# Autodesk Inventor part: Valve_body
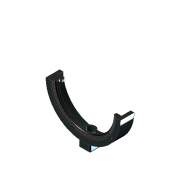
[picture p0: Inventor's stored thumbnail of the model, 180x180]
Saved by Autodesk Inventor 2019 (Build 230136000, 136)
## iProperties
Created: 2019-09
Part Number: Valve_body
Material: Steel, Cast
Document SubType Name: Modeling
Designer: Admin
Density: 7.85 g/cm^3
Appearance: Semi-Polished
Author: Admin
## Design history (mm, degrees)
sketch "Sketch1"
  geometry: L1 (0, 262.245)-(0, -275.534) reference; L2 (-162, 191.562)-(-162, -230.179); L3 (-147, -40.2)-(-162, -40.2); L4 (-162, -40.2)-(-162, 19.8); L5 (0, 0)-(-245.019, 0); L6 (-147, 0)-(-147, -40.2); L7 (-144, 19.8)-(-144, 14.657); L8 (-75.034, 9.8)-(-236.302, 9.8); L9 (-75.034, 14.657)-(-236.302, 14.657); L10 (-162, 19.8)-(-144, 19.8); L11 (-125, 9.8)-(-125, 0); L12 (-125, 0)-(-147, 0); L13 (-129.888, 17.396)-(-131.341, 17.768); L14 (-129.888, 17.396)-(-131.341, 17.768); L15 (-129.888, 17.396)-(-130.074, 16.67); L16 (-128.621, 16.298)-(-130.074, 16.67); L17 (-128.435, 17.025)-(-128.621, 16.298); L18 (-127.486, 16.782)-(-128.435, 17.025); L19 (-122.538, 20.488)-(-121.21, 24.915); L20 (-123.181, 9.313)-(-121.034, 17.713) reference; L21 (-123.286, 8.904)-(-119.75, 22.735); L22 (-146.331, 20.488)-(-146.331, 14.796); L23 (-125.304, -1.425)-(-149.651, -1.425); L24 (-146.331, 14.796)-(-125.304, 9.421); L25 (-121.21, 24.915)-(-124.087, 37.088); L26 (-125.304, 9.421)-(-125.304, -1.425); L27 (-123.644, 9.974)-(-123.644, 2.781); L28 (-123.644, 9.974)-(-118.392, 30.522) reference; L29 (-137.154, 19.254)-(-137.34, 18.527); L30 (-137.34, 18.527)-(-138.793, 18.899); L31 (-138.608, 19.625)-(-138.793, 18.899); L32 (-138.608, 19.625)-(-139.9, 19.956); L33 (-140.886, 16.097)-(-139.9, 19.956); L34 (-131.341, 17.768)-(-131.527, 17.041); L35 (-132.795, 18.139)-(-132.98, 17.413); L36 (-132.795, 18.139)-(-134.248, 18.511); L37 (-132.795, 18.139)-(-134.248, 18.511); L38 (-131.527, 17.041)-(-132.98, 17.413); L39 (-135.701, 18.882)-(-137.154, 19.254); L40 (-135.701, 18.882)-(-137.154, 19.254); L41 (-135.701, 18.882)-(-135.887, 18.156); L42 (-134.434, 17.784)-(-135.887, 18.156); L43 (-134.248, 18.511)-(-134.434, 17.784); L44 (-118.178, 12.338)-(-151.094, 20.753) reference; L45 (-141.514, 18.304)-(-141.131, 19.8); L46 (-144, 19.8)-(-141.131, 19.8); L47 (-144, 14.657)-(-138.677, 13.296); L48 (-128.477, 12.907)-(-129.425, 13.149); L49 (-129.425, 13.149)-(-129.24, 13.876); L50 (-129.24, 13.876)-(-130.693, 14.247); L51 (-130.879, 13.521)-(-130.693, 14.247); L52 (-130.879, 13.521)-(-132.332, 13.892); L53 (-132.332, 13.892)-(-132.146, 14.619); L54 (-132.146, 14.619)-(-133.6, 14.99); L55 (-133.785, 14.264)-(-133.6, 14.99); L56 (-133.785, 14.264)-(-135.239, 14.635); L57 (-135.239, 14.635)-(-135.053, 15.362); L58 (-135.053, 15.362)-(-136.506, 15.733); L59 (-136.692, 15.007)-(-136.506, 15.733); L60 (-136.692, 15.007)-(-138.145, 15.378); L61 (-138.145, 15.378)-(-137.959, 16.105); L62 (-137.959, 16.105)-(-139.413, 16.477); L63 (-139.598, 15.75)-(-139.413, 16.477); L64 (-139.598, 15.75)-(-140.89, 16.08)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; A1 r 4 centre (-126.495, 20.658) between (-127.486, 16.782) and (-124.45, 17.22); A2 r 4.5 centre (-122.148, 13.353) between (-121.034, 17.713) and (-124.45, 17.22); A3 r 4.17 centre (-122.148, 13.353) between (-125.656, 11.098) and (-123.181, 9.313); A4 r 4 centre (-129.02, 8.935) between (-125.656, 11.098) and (-128.03, 12.81); A5 r 7.167 centre (-123.225, 16.744) between (-129.425, 13.149) and (-125, 9.8); 3 further points
  constraints: 166 end point, 21 perpendicular, 18 symmetric about line, 11 point on circle, 10 point on line, 8 tangent, 6 collinear, 5 centre point, 5 horizontal, 5 vertical, 3 parallel, 1 midpoint, 5 other
  dimensions: "d0" = 162 distance between parallel lines of L2 L1; "d3" = 15 distance between parallel lines of L2 L6; "d4" = 18 distance between parallel lines of L2 L7; "d6" = 9.8 distance between parallel lines of L8 L5; "d8" = 5.143 distance between parallel lines of L9 L10; "d9" = 22 distance between parallel lines of L6 L11; "d10" = 60 distance of L3.end L4.end; "d157" = 2 distance between parallel lines of L32 L44; "d174" = 90 deg angle of L49 L48; "d175" = 19.8 distance between parallel lines of L5 L10; "d176" = 14.657 distance from line of L12 L7.end (derived); "d177" = 9.8 distance of L11.end L11.start (derived); "d178" = 7.16694 radius of A5 (derived); "d179" = 1.5 distance between parallel lines of L51 L49; "d180" = 1.45327 horizontal distance of L51.start L52.end; "d181" = 1.5 distance between parallel lines of L55 L53; "d182" = 1.45327 horizontal distance of L55.start L56.end; "d183" = 1.5 distance between parallel lines of L59 L57; "d184" = 1.45327 horizontal distance of L59.start L60.end; "d185" = 1.5 distance between parallel lines of L63 L61; "d186" = 1.29211 horizontal distance of L63.start L64.end; "d187" = 0.75 distance between parallel lines of L72 L56; "d188" = 0.75 distance between parallel lines of L58 L60; "d189" = 0.75 distance between parallel lines of L62 L82; "d191" = 120 deg angle of L83 L64; "d192" = 150 deg angle of L45 L83 (derived); "d193" = 13.35338 distance from line of L5 A2.centre; "d194" = 122.14822 distance from line of L1 A2.centre (derived); "d195" = 14.3395 deg angle of L5 L44 (derived)
revolve "Revolution1" sketch "Sketch1" stored, may be unused: angle "d11" = 90 deg
workplane "Work Plane1"
sketch "Sketch2"
  geometry: L1 (223.402, 3.8)-(-305.572, 3.8); L2 (0, -179.354)-(0, 85.571); L3 (218.703, -10.2)-(-257.343, -10.2); L4 (22.5, -10.2)-(22.5, 3.8); L5 (-22.5, -10.2)-(-22.5, 3.8); L6 (22.5, 3.8)-(-22.5, 3.8); A1 r 22.5 centre (0, -10.2) between (-22.5, -10.2) and (22.5, -10.2); 1 further point
  constraints: 12 end point, 6 point on line, 3 horizontal, 2 perpendicular, 2 point on circle, 2 tangent, 1 centre point, 1 vertical
  dimensions: "d14" = 3.8 distance from line of point (0, 0) L1; "d15" = 0 distance from line of point (0, 0) L2; "d16" = 14 distance between parallel lines of L1 L3; "d17" = 45 diameter of A1
extrude "Extrusion1" join sketch "Sketch2" distance "d19" = 7; taper "d21" = 0 deg; dims "d20" = 15, "d22" = 0
workplane "Work Plane2"
sketch "Sketch4"
  geometry: L1 (0, 0)-(0, -201.68); L2 (32, 0)-(32, -215.896); L3 (-32, 0)-(-32, -211.964); L4 (22.5, -128)-(22.5, -145.268) reference; L5 (-22.5, -145.268)-(-22.5, -128) reference; L6 (22.5, -128)-(-22.5, -128); A1 r 10 centre (22.41, -118) between (22.5, -128) and (32, -120.835); A2 r 10 centre (-22.41, -118) between (-32, -120.835) and (-22.5, -128); A3 r 125 centre (0, 0) between (-32, -120.835) and (32, -120.835)
  constraints: 8 end point, 6 point on circle, 3 centre point, 2 point on line, 2 vertical, 1 parallel, 1 perpendicular
  dimensions: "d33" = 32 distance between parallel lines of L1 L2; "d34" = 32 distance between parallel lines of L1 L3; "d35" = 10 radius of A1; "d36" = 10 radius of A2; "d37" = 7.1654 distance from line of A2.start L6; "d38" = 7.1654 distance from line of L6 A1.end; "d39" = 125 radius of A3
extrude "Extrusion2" cut sketch "Sketch4" stored distance "d40" = 11.61; taper "d41" = 0 deg
workplane "Work Plane3"
sketch "Sketch5"
  geometry: L1 (-25, -35.2)-(25, -35.2); L2 (25, -35.2)-(25, 14.8); L3 (25, 14.8)-(-25, 14.8); L4 (-25, 14.8)-(-25, -35.2); L5 (162, 19.8)-(-162, 19.8) reference; L6 (-64.969, -10.2)-(71.172, -10.2); L7 (0, 58.935)-(0, -84.464); C1 r 2.5 at (-18, 7.8); C2 r 2.5 at (-18, -28.2); C3 r 2.5 at (18, -28.2); C4 r 2.5 at (18, 7.8); 5 further points
  constraints: 12 end point, 4 centre point, 2 coincident, 2 horizontal, 2 parallel, 2 point on line, 1 perpendicular, 1 vertical, 11 other
  dimensions: "d43" = 5 distance between parallel lines of L5 L3; "d44" = 50 distance between parallel lines of L3 L1; "d45" = 50 distance between parallel lines of L2 L4; "d46" = 25 distance from line of L4 point (0, 0); "d47" = 25 distance between parallel lines of L1 L6; "d48" = 25 distance between parallel lines of L4 L7; "d49" = 5 diameter of C1; "d50" = 7 distance from line of L4 C1.centre; "d51" = 7 distance from line of L3 C1.centre; "d54" = 360 deg dimension on point (0, -10.2) C1.centre (derived)
extrude "Extrusion3" join sketch "Sketch5" stored distance "d56" = 11.61; taper "d57" = 0 deg
mirror "Mirror1"
mirror "Mirror2"
workplane "Work Plane5"
  workplane "Work Plane4"
sketch "Sketch6"
  geometry: L1 (197.807, 0)-(-221.446, 0) reference; L2 (94.463, -10.2)-(-97.803, -10.2); L3 (0, -127.712)-(0, 109.699) reference; L4 (77.5, -45.2)-(-77.5, -45.2); L5 (-77.5, -45.2)-(-77.5, 14.8); L6 (-77.5, 14.8)-(77.5, 14.8); L7 (77.5, 14.8)-(77.5, -45.2); L8 (-77.5, 14.8)-(-74.676, 14.8); L9 (-74.676, 14.8)-(-74.676, 9.772); L10 (-74.676, 9.772)-(-77.5, 9.772); L11 (-77.5, 9.772)-(-77.5, 14.8); L12 (10.187, -41.522)-(70.896, -19.606); L13 (10.187, 21.122)-(70.896, -0.794); L14 (-10.187, -41.522)-(-70.896, -19.606); L15 (-10.187, 21.122)-(-70.896, -0.794); C1 r 5 at (67.5, -10.2); C2 r 5 at (-67.5, -10.2); A1 r 10 centre (67.5, -10.2) between (70.896, -19.606) and (70.896, -0.794); A2 r 10 centre (-67.5, -10.2) between (-70.896, -0.794) and (-70.896, -19.606); A3 r 30 centre (0, -13.305) between (-10.187, -41.522) and (10.187, -41.522); A4 r 30 centre (0, -7.095) between (10.187, 21.122) and (-10.187, 21.122); 3 further points
  constraints: 30 end point, 8 point on circle, 6 centre point, 6 tangent, 5 horizontal, 5 point on line, 5 symmetric about line, 4 parallel, 2 coincident, 2 perpendicular, 2 vertical, 1 midpoint, 1 other
  dimensions: "d59" = 10.2 distance between parallel lines of L1 L2; "d60" = 155 distance between parallel lines of L5 L7; "d61" = 60 distance between parallel lines of L6 L4; "d62" = 77.5 distance between parallel lines of L3 L5; "d63" = 25 distance between parallel lines of L2 L6; "d64" = 20 diameter of A1; "d65" = 30 radius of A3; "d66" = 30 radius of A4; "d67" = 10 diameter of C1; "d68" = 10 diameter of C2
extrude "Extrusion4" join sketch "Sketch6" distance "d69" = 20; taper "d70" = 0 deg
sketch "Sketch7"
  geometry: L1 (-67.5, -10.2)-(67.5, -10.2); L2 (0, -193.472)-(0, 171.018); L3 (37.5, -51.446)-(37.5, 40.462); L4 (-37.5, -59.616)-(-37.5, 46.96); L5 (-112.757, 4.8)-(112.291, 4.8); L6 (-106.821, -25.2)-(102.576, -25.2); L7 (3.943, 13.99)-(41.048, -1.929); L8 (3.943, -34.39)-(41.048, -18.471); L9 (-3.943, 13.99)-(-41.048, -1.929); L10 (-3.943, -34.39)-(-41.048, -18.471); C1 r 5 at (-67.5, -10.2) reference; C2 r 5 at (67.5, -10.2) reference; A1 r 10 centre (0, -25.2) between (-3.943, -34.39) and (3.943, -34.39); A2 r 10 centre (0, 4.8) between (3.943, 13.99) and (-3.943, 13.99); A3 r 9 centre (-37.5, -10.2) between (-41.048, -1.929) and (-41.048, -18.471); A4 r 9 centre (37.5, -10.2) between (41.048, -18.471) and (41.048, -1.929); 1 further point
  constraints: 20 end point, 8 point on circle, 6 symmetric about line, 5 tangent, 4 centre point, 4 point on line, 3 horizontal, 3 vertical
  dimensions: "d72" = 30 distance from line of L1.end L3; "d73" = 30 distance from line of L4 L1.start; "d120" = 20 diameter of A1; "d121" = 20 diameter of A2; "d122" = 133.56 deg angle of L9 L7; "d123" = 133.56 deg angle of L10 L8 (derived); "d124" = 9 radius of A4
sketch "Sketch8"
  geometry: L1 (-0.75, -110.417)-(-0.75, 93.124); L2 (6.647, -10.2)-(-12.422, -10.2); C1 r 17.45 at (-0.75, -10.2); A1 r 22.5 centre (0, -10.2) between (-22.5, -10.2) and (22.5, -10.2) reference; 1 further point
  constraints: 4 end point, 3 point on line, 1 centre point, 1 horizontal, 1 vertical
  dimensions: "d79" = 0.75 distance from line of A1.centre L1; "d80" = 34.9 diameter of C1
extrude "Extrusion6" cut sketch "Sketch8" stored distance "d81" = 589.9125; taper "d82" = 0 deg
sketch "Sketch10"
  geometry: C1 r 2.5 at (152.5, 0); 1 further point
  constraints: 1 centre point
  dimensions: "d88" = 5 diameter of C1; "d89" = 152.5 distance of point (0, 0) C1.centre; "d90" = 0 vertical distance of point (0, 0) C1.centre
extrude "Extrusion7" cut sketch "Sketch10" distance "d91" = 5; taper "d92" = 0 deg
pattern_circular "Circular Pattern1" dims angle "d94" = 360 deg
sketch "Sketch11"
  geometry: L1 (147, 0)-(22.5, 0) reference; L2 (147, -40.2)-(-147, -40.2) reference; L3 (147, 0)-(147, -40.2) reference; L4 (125, -5.584)-(117, -5.584); L5 (117, -5.584)-(117, -13.584); L6 (125, -22.435)-(147, -22.435); L7 (147, -22.435)-(147, -5.584); L8 (153.058, -13.584)-(96.589, -13.584); L9 (125, 3.711)-(125, -68.159); L10 (117, -13.584)-(125, -22.435); L11 (125, -5.584)-(125, 0); L12 (125, 0)-(147, 0); L13 (147, 0)-(147, -5.584); 1 further point
  constraints: 20 end point, 5 point on line, 3 parallel, 2 horizontal, 1 perpendicular, 1 vertical
  dimensions: "d96" = 30 distance between parallel lines of L5 L7; "d97" = 8 distance between parallel lines of L8 L4; "d99" = 22.43458 distance between parallel lines of L1 L6; "d100" = 22 distance between parallel lines of L11 L13; "d101" = 5.58367 distance of L4.start L11.end
extrude "Extrusion8" join sketch "Sketch11" stored distance "d102" = 20; taper "d103" = 0 deg
fillet "Fillet2" dims "d105" = 5
fillet "Fillet4" dims "d107" = 5
workplane "Work Plane7"
sketch "Sketch13"
  geometry: C1 r 17.45 at (0.75, 10.2) reference; C2 r 19 at (0.75, 10.2); 1 further point
  constraints: 1 centre point, 1 coincident
  dimensions: "d113" = 38 diameter of C2
extrude "Extrusion11" join sketch "Sketch7" stored distance "d125" = 30; taper "d126" = 0 deg
workplane "Work Plane8"
sketch "Sketch14"
  geometry: C1 r 17.45 at (0, 0) reference; 1 further point
extrude "Extrusion12" cut sketch "Sketch14" distance "d127" = 141.45; taper "d128" = 0 deg
extrude "Extrusion13" cut sketch "Sketch13" distance "d133" = 30; taper "d134" = 0 deg
sketch "Sketch15"
  geometry: C1 r 17.45 at (0, 0) reference; C2 r 19 at (0, 0) reference; 1 further point
extrude "Extrusion14" new body sketch "Sketch15" distance "d135" = 7; taper "d136" = 0 deg
chamfer "Chamfer1" distance "d137" = 0.5; stored, may be unused: second distance "d138" = 2, angle "d139" = 45 deg
chamfer "Chamfer2" distance "d140" = 0.5; stored, may be unused: second distance "d141" = 2, angle "d142" = 45 deg
pattern_linear "Rectangular Pattern1" dims "d145" = 7
sketch "Sketch16"
  geometry: C1 r 19 at (0, 0) reference; C2 r 17.45 at (0, 0) reference; 1 further point
extrude "Extrusion15" new body sketch "Sketch16" stored distance "d146" = 3; taper "d147" = 0 deg
body "Solid1"
body "Solid2"
feature "Pattern of Solid2:1"
body "Solid3"
feature "Pattern of Solid2:2"
body "Solid4"
feature "Pattern of Solid2:3"
body "Solid5"
body "Solid6"
other parameters: "d2" = 19.8, "d5" = 37, "d7" = 5.143, "d12" = -135, "d23" = 5.7, "d42" = -196, "d58" = -212, "d71" = 42, "d83" = 0.5, "d84" = 2, "d85" = 0, "d112" = -6.5, "d116" = 18, "d129" = 0.5, "d130" = 2, "d131" = 0
